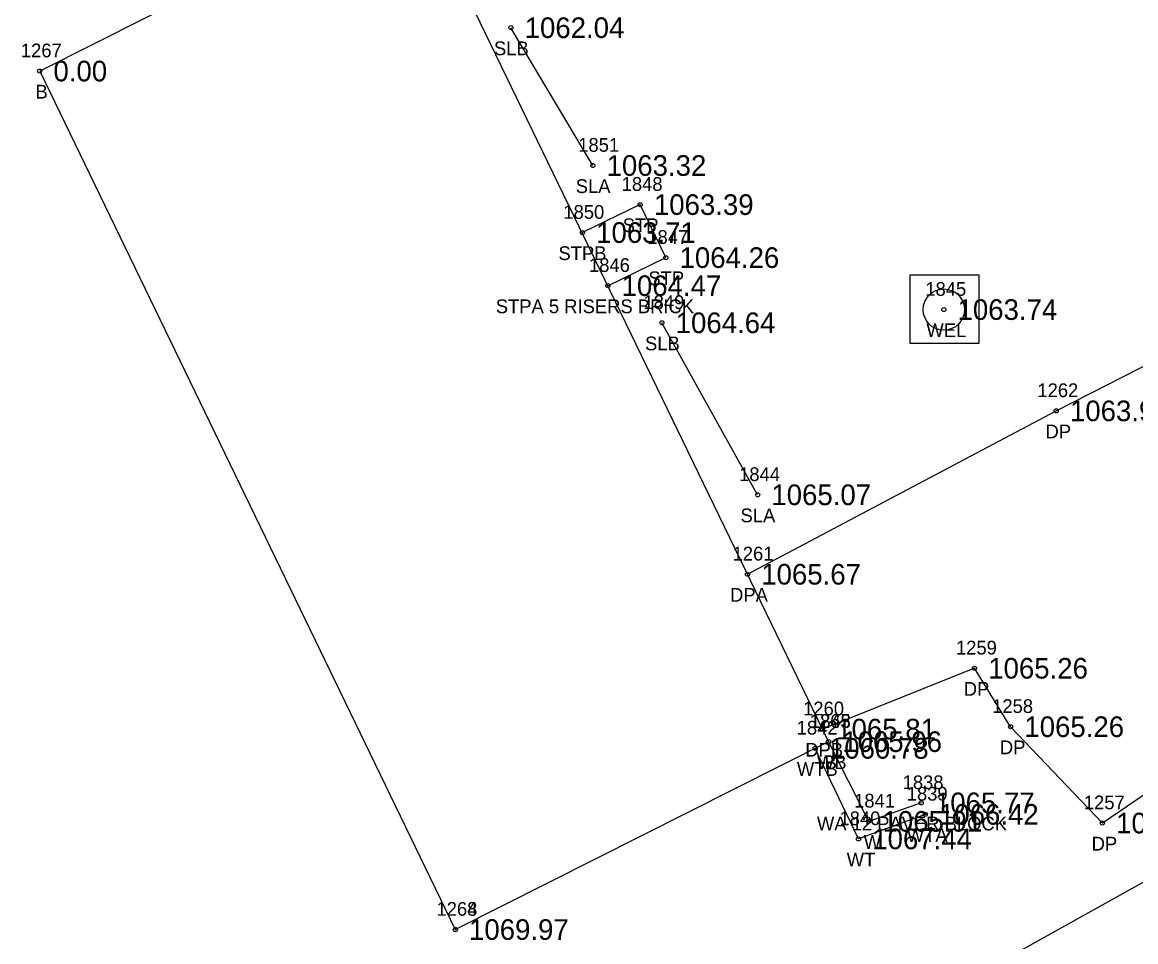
# Model space of a CAD drawing. Extents: x 1578957 to 1581675, y 1115963 to 1120391.
# Drawn here: x 1580194 to 1580275, y 1116727.6 to 1116794.5 of the extents above; entities that cross this region are included whole.
import ezdxf

# ---------------------------------------------------------------- set-up
doc = ezdxf.new("R2010")
doc.units = 0
for name, color, linetype in [('RD_EX_Bldg', 7, 'Continuous'), ('RD_EX_Bldg_txCode', 7, 'Continuous'), ('RD_EX_BldgApp', 7, 'Continuous'), ('RD_EX_BldgApp_txCode', 7, 'Continuous'), ('RD_EX_Conc', 7, 'Continuous'), ('RD_EX_Conc_txCode', 7, 'Continuous'), ('RD_EX_Driveway', 7, 'Continuous'), ('RD_EX_Driveway_txCode', 7, 'Continuous'), ('RD_EX_Misc', 7, 'Continuous'), ('RD_EX_Misc_txCode', 7, 'Continuous'), ('RD_EX_SU_H2O', 7, 'Continuous'), ('RD_EX_TX_Bldg_ELEV', 7, 'Continuous'), ('RD_EX_TX_BldgApp_ELEV', 7, 'Continuous'), ('RD_EX_TX_Conc_ELEV', 7, 'Continuous'), ('RD_EX_TX_Driveway_ELEV', 7, 'Continuous'), ('RD_EX_TX_Misc_ELEV', 7, 'Continuous'), ('RD_EX_TX_VEG_ELEV', 7, 'Continuous'), ('RD_EX_VEG', 7, 'Continuous'), ('RD_EX_VEG_txCode', 7, 'Continuous'), ('RD_HC_Cl', 7, 'Continuous'), ('RD_SMD_Locator', 7, 'Continuous')]:
    doc.layers.add(name, color=color, linetype=linetype)

msp = doc.modelspace()

# ---------------------------------------------------------------- linework, layer by layer
at = {"layer": 'RD_EX_Bldg'}
msp.add_lwpolyline([(1580225.532, 1116728.528), (1580252.679, 1116742.195), (1580222.453, 1116804.638), (1580195.306, 1116790.97), (1580225.532, 1116728.528)], dxfattribs=at)
at = {"layer": 'RD_EX_BldgApp'}
msp.add_lwpolyline([(1580259.415, 1116737.741), (1580255.602, 1116736.398), (1580252.679, 1116742.195)], dxfattribs=at)
at = {"layer": 'RD_EX_BldgApp_txCode'}
msp.add_circle((1580261.061, 1116773.622), 0.15, dxfattribs=at)
at = {"layer": 'RD_EX_Conc'}
msp.add_lwpolyline([(1580236.626, 1116775.36), (1580240.842, 1116777.401), (1580238.976, 1116781.256), (1580234.776, 1116779.223)], dxfattribs=at)
at = {"layer": 'RD_EX_Driveway'}
for points in [[(1580246.785, 1116754.371), (1580269.236, 1116766.255), (1580288.728, 1116776.196), (1580304.812, 1116786.681)], [(1580314.767, 1116769.462), (1580305.425, 1116768.544), (1580290.155, 1116762.023), (1580282.47, 1116756.048), (1580280.869, 1116741.895), (1580272.593, 1116736.273), (1580265.92, 1116743.28), (1580263.292, 1116747.533), (1580252.238, 1116743.106)]]:
    msp.add_lwpolyline(points, dxfattribs=at)
at = {"layer": 'RD_EX_Misc'}
msp.add_lwpolyline([(1580259.712, 1116736.906), (1580254.858, 1116735.12), (1580251.706, 1116741.706)], dxfattribs=at)
at = {"layer": 'RD_EX_SU_H2O'}
msp.add_lwpolyline([(1580258.608, 1116771.15), (1580258.608, 1116776.15), (1580263.608, 1116776.15), (1580263.608, 1116771.15)], close=True, dxfattribs=at)
msp.add_circle((1580261.061, 1116773.622), 1.5, dxfattribs=at)
at = {"layer": 'RD_EX_VEG'}
for p, q in [((1580235.536, 1116784.1), (1580229.576, 1116794.123)), ((1580247.52, 1116760.15), (1580240.56, 1116772.661))]:
    msp.add_line(p, q, dxfattribs=at)
msp.add_lwpolyline([(1580267.269, 1116691.725), (1580298.494, 1116705.202), (1580314.833, 1116697.513), (1580311.162, 1116695.924), (1580292.398, 1116742.225), (1580281.51, 1116735.283), (1580235.086, 1116709.395)], dxfattribs=at)
at = {"layer": 'RD_HC_Cl'}
msp.add_arc((1578700.887, 1115846.201), 1869.668, 25.909481, 32.948945, dxfattribs=at)
at = {"layer": 'RD_SMD_Locator'}
for centre in [(1580229.576, 1116794.123), (1580195.306, 1116790.97), (1580235.536, 1116784.1), (1580238.976, 1116781.256), (1580234.776, 1116779.223), (1580240.842, 1116777.401), (1580236.626, 1116775.36), (1580240.56, 1116772.661), (1580269.236, 1116766.255), (1580247.52, 1116760.15), (1580246.785, 1116754.371), (1580263.292, 1116747.533), (1580252.238, 1116743.106), (1580265.92, 1116743.28), (1580251.706, 1116741.706), (1580252.679, 1116742.195), (1580252.679, 1116742.195), (1580259.415, 1116737.741), (1580259.712, 1116736.906), (1580255.602, 1116736.398), (1580272.593, 1116736.273), (1580254.858, 1116735.12), (1580225.532, 1116728.528), (1580225.532, 1116728.528)]:
    msp.add_circle(centre, 0.15, dxfattribs=at)

# ---------------------------------------------------------------- texts
at = {"layer": 'RD_EX_Bldg_txCode'}
for s, p in [('1267', (1580193.936, 1116791.97)), ('B', (1580194.999, 1116788.97)), ('1265', (1580251.309, 1116743.195)), ('B', (1580252.372, 1116740.195)), ('1264', (1580224.162, 1116729.528)), ('1268', (1580224.162, 1116729.528))]:
    msp.add_text(s, height=1, dxfattribs=at).set_placement(p)
at = {"layer": 'RD_EX_BldgApp_txCode'}
for s, p in [('1845', (1580259.715, 1116774.622)), ('WEL', (1580259.793, 1116771.622))]:
    msp.add_text(s, height=1, dxfattribs=at).set_placement(p)
at = {"layer": 'RD_EX_Conc_txCode'}
for s, p in [('1848', (1580237.63, 1116782.256)), ('1850', (1580233.39, 1116780.223)), ('STP', (1580237.708, 1116779.256)), ('1847', (1580239.496, 1116778.401)), ('STPB', (1580233.035, 1116777.223)), ('1846', (1580235.255, 1116776.36)), ('STP', (1580239.575, 1116775.401)), ('STPA 5 RISERS BRICK', (1580228.476, 1116773.36))]:
    msp.add_text(s, height=1, dxfattribs=at).set_placement(p)
at = {"layer": 'RD_EX_Driveway_txCode'}
for s, p in [('1262', (1580267.866, 1116767.255)), ('DP', (1580268.457, 1116764.255)), ('1261', (1580245.698, 1116755.371)), ('DPA', (1580245.517, 1116752.371)), ('1259', (1580261.945, 1116748.533)), ('DP', (1580262.512, 1116745.533)), ('1260', (1580250.828, 1116744.106)), ('1258', (1580264.574, 1116744.28)), ('DPB', (1580250.986, 1116741.106)), ('DP', (1580265.141, 1116741.28)), ('1257', (1580271.246, 1116737.273)), ('DP', (1580271.813, 1116734.273))]:
    msp.add_text(s, height=1, dxfattribs=at).set_placement(p)
at = {"layer": 'RD_EX_Misc_txCode'}
for s, p in [('1843', (1580251.332, 1116743.195)), ('1842', (1580250.359, 1116742.706)), ('WB', (1580251.836, 1116740.195)), ('WTB', (1580250.375, 1116739.706)), ('1838', (1580258.068, 1116738.741)), ('1841', (1580254.539, 1116737.398)), ('1839', (1580258.365, 1116737.906)), ('1840', (1580253.472, 1116736.12)), ('WA 12 PAVER BLOCK', (1580251.832, 1116735.741)), ('W', (1580255.232, 1116734.398)), ('WTA', (1580258.365, 1116734.906)), ('WT', (1580253.999, 1116733.12))]:
    msp.add_text(s, height=1, dxfattribs=at).set_placement(p)
at = {"layer": 'RD_EX_TX_Bldg_ELEV'}
for s, p in [('0.00', (1580196.306, 1116790.22)), ('1065.96', (1580253.679, 1116741.445)), ('1069.97', (1580226.532, 1116727.778)), ('1069.97', (1580226.532, 1116727.778))]:
    msp.add_text(s, height=1.5, dxfattribs=at).set_placement(p)
at = {"layer": 'RD_EX_TX_BldgApp_ELEV'}
msp.add_text('1063.74', height=1.5, dxfattribs=at).set_placement((1580262.061, 1116772.872))
at = {"layer": 'RD_EX_TX_Conc_ELEV'}
for s, p in [('1063.39', (1580239.976, 1116780.506)), ('1063.71', (1580235.776, 1116778.473)), ('1064.26', (1580241.842, 1116776.651)), ('1064.47', (1580237.626, 1116774.61))]:
    msp.add_text(s, height=1.5, dxfattribs=at).set_placement(p)
at = {"layer": 'RD_EX_TX_Driveway_ELEV'}
for s, p in [('1063.93', (1580270.236, 1116765.505)), ('1065.67', (1580247.785, 1116753.621)), ('1065.26', (1580264.292, 1116746.783)), ('1065.26', (1580266.92, 1116742.53)), ('1065.81', (1580253.238, 1116742.356)), ('1065.70', (1580273.593, 1116735.523))]:
    msp.add_text(s, height=1.5, dxfattribs=at).set_placement(p)
at = {"layer": 'RD_EX_TX_Misc_ELEV'}
for s, p in [('1060.78', (1580252.706, 1116740.956)), ('1065.96', (1580253.679, 1116741.445)), ('1065.77', (1580260.415, 1116736.991)), ('1066.42', (1580260.712, 1116736.156)), ('1065.91', (1580256.602, 1116735.648)), ('1067.44', (1580255.858, 1116734.37))]:
    msp.add_text(s, height=1.5, dxfattribs=at).set_placement(p)
at = {"layer": 'RD_EX_TX_VEG_ELEV'}
for s, p in [('1062.04', (1580230.576, 1116793.373)), ('1063.32', (1580236.536, 1116783.35)), ('1064.64', (1580241.56, 1116771.911)), ('1065.07', (1580248.52, 1116759.4))]:
    msp.add_text(s, height=1.5, dxfattribs=at).set_placement(p)
at = {"layer": 'RD_EX_VEG_txCode'}
for s, p in [('SLB', (1580228.347, 1116792.123)), ('1851', (1580234.473, 1116785.1)), ('SLA', (1580234.292, 1116782.1)), ('1849', (1580239.214, 1116773.661)), ('SLB', (1580239.332, 1116770.661)), ('1844', (1580246.174, 1116761.15)), ('SLA', (1580246.276, 1116758.15))]:
    msp.add_text(s, height=1, dxfattribs=at).set_placement(p)

doc.saveas('drawing.dxf')
